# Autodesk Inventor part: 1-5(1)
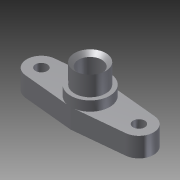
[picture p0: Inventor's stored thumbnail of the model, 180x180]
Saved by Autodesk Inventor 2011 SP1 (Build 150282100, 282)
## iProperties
Created: 2014-01
Part Number: 1-5(1)
Document SubType Name: Modeling
Designer: Administrator
Density: 1 g/cm^3
Author: Administrator
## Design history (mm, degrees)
sketch "草图1"
  geometry: L1 (0, 10)-(-25.736, 7.464); L2 (0, -10)-(-25.736, -7.464); L3 (0, 10)-(25.736, 7.464); L4 (0, -10)-(25.736, -7.464); A1 r 7.5 centre (-25, 0) between (-25.736, 7.464) and (-25.736, -7.464); A2 r 7.5 centre (25, 0) between (25.736, -7.464) and (25.736, 7.464); 1 further point
  constraints: 8 end point, 4 point on circle, 4 tangent, 2 centre point
  dimensions: "d2" = 15 diameter of A1; "d4" = 15 diameter of A2
extrude "拉伸1" new body sketch "草图1" distance "d5" = 10; taper "d6" = 0 deg
sketch "草图2"
  geometry: C1 r 10 at (0, 0); 1 further point
  constraints: 1 centre point, 1 coincident
extrude "拉伸2" join sketch "草图2" distance "d7" = 5; taper "d8" = 0 deg
sketch "草图3"
  geometry: C1 r 10 at (0, 0) reference; C2 r 8 at (0, 0)
  constraints: 1 centre point, 1 coincident
  dimensions: "d9" = 16 diameter of C2
extrude "拉伸3" join sketch "草图3" distance "d10" = 10; taper "d11" = 0 deg
sketch "草图4"
  geometry: C1 r 8 at (0, 0); 1 further point
  constraints: 1 centre point, 1 coincident
  dimensions: "d12" = 16 diameter of C1
extrude "拉伸4" cut sketch "草图4" distance "d13" = 3; taper "d14" = 0 deg
sketch "草图5"
  geometry: C1 r 8 at (0, 0) reference; C2 r 6 at (0, 0)
  constraints: 1 centre point, 1 coincident
  dimensions: "d15" = 12 diameter of C2
extrude "拉伸5" cut sketch "草图5" stored distance "d16" = 3; taper "d17" = 0 deg
chamfer "倒角1" distance "d18" = 2; stored, may be unused: second distance "d19" = 2, angle "d20" = 45 deg
sketch "草图6"
  geometry: C1 r 5 at (-25, 0); C2 r 5 at (25, 0); A1 r 7.5 centre (-25, 0) between (-25.736, 7.464) and (-25.736, -7.464) reference; A2 r 7.5 centre (25, 0) between (25.736, -7.464) and (25.736, 7.464) reference
  constraints: 2 centre point, 2 coincident
  dimensions: "d21" = 10 diameter of C1; "d22" = 10 diameter of C2
extrude "拉伸6" cut sketch "草图6" distance "d23" = 4; taper "d24" = 0 deg
hole "Hole1" diameter "d27" = 6; stored, may be unused: countersink angle "d31" = 90 deg, drill point angle "d33" = 0 deg; dims "d25" = 10, "d26" = 10, "d28" = 6, "d29" = 4, "d30" = 2, "d32" = 6
hole "Hole2" diameter "d36" = 6; stored, may be unused: countersink angle "d40" = 90 deg, drill point angle "d42" = 118 deg; dims "d34" = 10, "d35" = 10, "d37" = 6, "d38" = 4, "d39" = 2, "d41" = 6
node "实体1"
